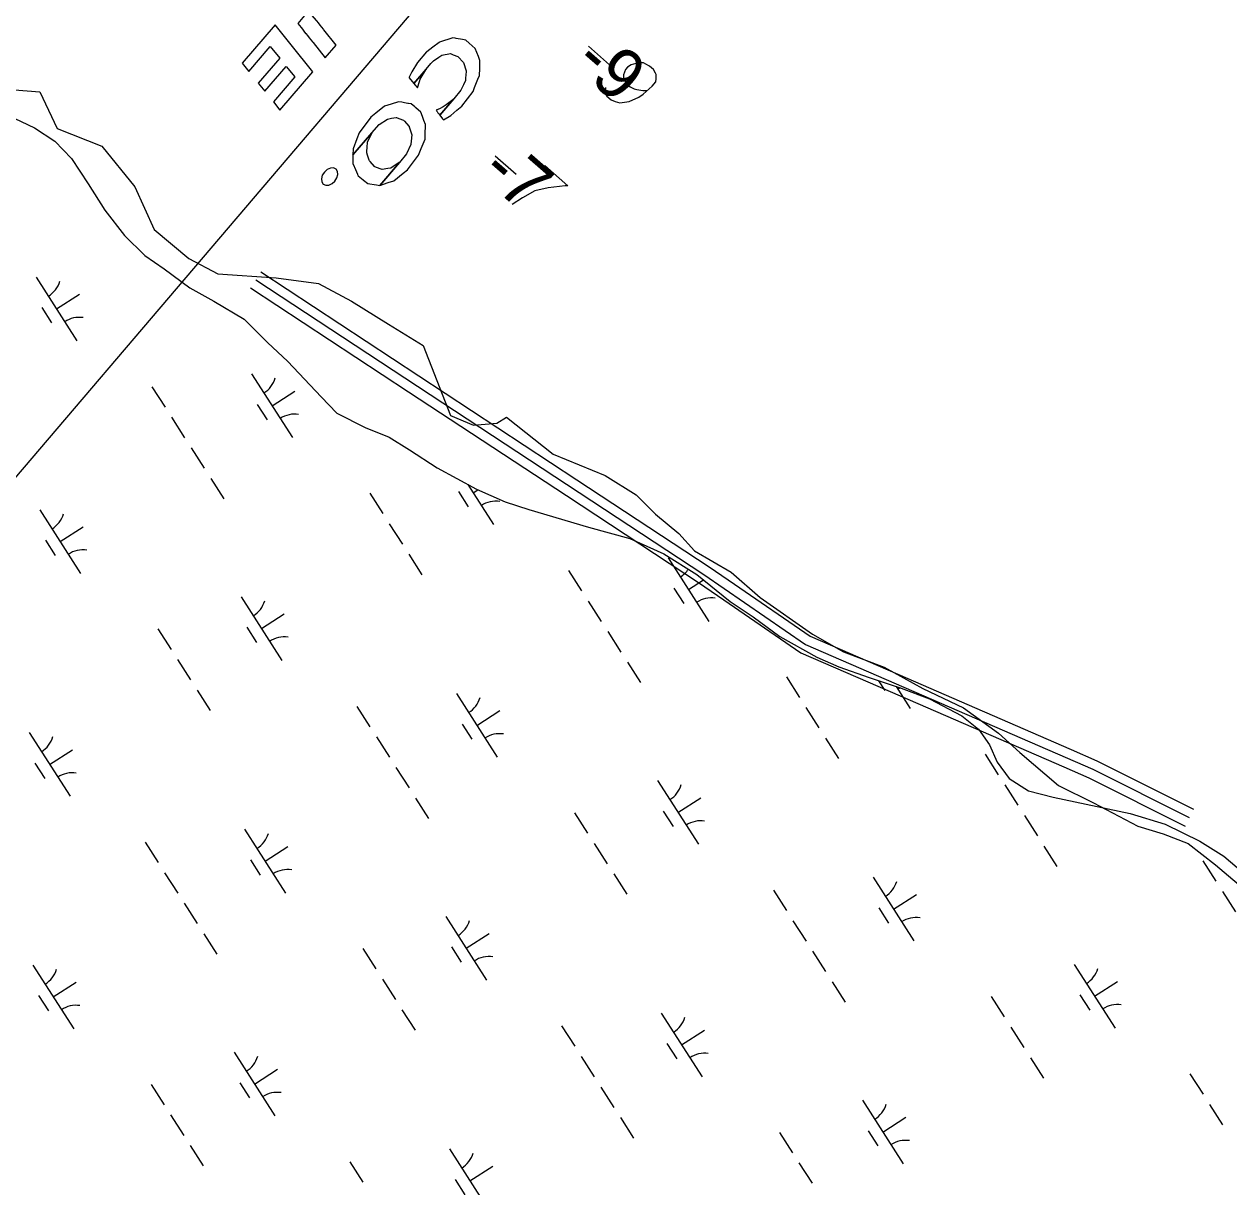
# Model space of a CAD drawing. Extents: x 3962991 to 3983549, y 181631 to 204078.
# Drawn here: x 3970099 to 3970895, y 195515 to 196284 of the extents above; entities that cross this region are included whole.
import ezdxf

# ---------------------------------------------------------------- set-up
doc = ezdxf.new("R2010")
doc.units = 0
for name, color, linetype in [('V-ANNO-MASK', 7, 'Continuous'), ('V-ANNO-MASK2', 7, 'Continuous'), ('V-RIVR-EDGE', 7, 'Continuous'), ('V-RIVR-IDEN', 7, 'Continuous'), ('V-RIVR-RANG', 7, 'Continuous'), ('V-UTIL-LINE', 7, 'Continuous'), ('V-WETL-SWMP', 7, 'Continuous')]:
    doc.layers.add(name, color=color, linetype=linetype)

msp = doc.modelspace()

# ---------------------------------------------------------------- linework, layer by layer
at = {"layer": 'V-ANNO-MASK2'}
for p, q in [((3970471.96, 196269.11), (3970485.89, 196256.98)), ((3970410.21, 196196.77), (3970424.14, 196184.65))]:
    msp.add_line(p, q, dxfattribs=at)
for points in [[(3970288.91, 196289.67), (3970286.47, 196292.07), (3970279.72, 196284.21), (3970281.89, 196281.5), (3970282.1, 196281.24), (3970284.93, 196277.7), (3970285.01, 196277.6), (3970286.13, 196276.2), (3970287.37, 196274.64), (3970289.48, 196272.02), (3970289.82, 196271.59), (3970289.82, 196271.59), (3970297.83, 196261.57), (3970305.05, 196269.96), (3970297.05, 196280.01), (3970296.72, 196280.44), (3970294.61, 196283.07), (3970293.37, 196284.63), (3970292.25, 196286.02), (3970292.17, 196286.12), (3970289.15, 196289.44)], [(3970269.16, 196277.88), (3970264.74, 196283.39), (3970242.98, 196258.08), (3970247.4, 196252.55), (3970261.57, 196269.05), (3970267.82, 196261.26), (3970253.64, 196244.77), (3970257.96, 196239.38), (3970272.13, 196255.87), (3970277.75, 196248.84), (3970263.58, 196232.35), (3970267.98, 196226.83), (3970289.74, 196252.15), (3970285.33, 196257.66), (3970279.71, 196264.69), (3970275.4, 196270.08)], [(3970365.05, 196265.51), (3970364.95, 196265.43), (3970358.93, 196258.33), (3970355.06, 196252.17), (3970353.47, 196248.63), (3970353.29, 196248.25), (3970356.52, 196244.5), (3970364.55, 196253.92), (3970367.81, 196257.67), (3970369.44, 196259.54), (3970373.12, 196261.95), (3970374.97, 196263.17), (3970380.72, 196264.29), (3970382.6, 196263.58), (3970385.57, 196262.45), (3970389.22, 196258.48), (3970389.29, 196258.4), (3970391.06, 196252.82), (3970390.83, 196249.85), (3970390.73, 196248.53), (3970390.69, 196248.04), (3970390.56, 196246.44), (3970389.28, 196243.63), (3970387.64, 196240.09), (3970382.99, 196234.37), (3970373.73, 196223.51), (3970375.46, 196221.25), (3970375.99, 196220.57), (3970380.86, 196223.32), (3970385.01, 196226.85), (3970388.23, 196229.6), (3970388.24, 196229.6), (3970395.64, 196239.32), (3970396.65, 196241.84), (3970398.89, 196247.44), (3970399.87, 196249.88), (3970400.03, 196254.36), (3970400.04, 196254.63), (3970400.1, 196256.33), (3970400.15, 196257.68), (3970400.2, 196259.19), (3970400.22, 196259.66), (3970399.9, 196260.48), (3970399.17, 196262.34), (3970397.12, 196267.58), (3970397.08, 196267.69), (3970393.05, 196271.22), (3970390.79, 196273.19), (3970388.63, 196273.58), (3970384.47, 196274.3), (3970383.76, 196274.43), (3970382.35, 196274.68), (3970382.32, 196274.68), (3970382.23, 196274.65), (3970373.35, 196271.78), (3970373.14, 196271.71), (3970369.04, 196268.57)], [(3970364.41, 196253.67), (3970364.55, 196253.92), (3970356.52, 196244.5), (3970356.56, 196244.47), (3970356.58, 196244.45), (3970357.39, 196243.5), (3970357.81, 196243.03), (3970358.89, 196241.75), (3970360.27, 196245.91), (3970360.78, 196247.48), (3970364.33, 196253.55)], [(3970331.33, 196224.88), (3970327.94, 196222.18), (3970320.3, 196211.94), (3970318.83, 196208.02), (3970316.35, 196201.42), (3970316.24, 196197.28), (3970328.68, 196211.87), (3970333.47, 196217.41), (3970339, 196221.03), (3970339.15, 196221.06), (3970341.61, 196221.54), (3970341.62, 196221.55), (3970344.75, 196222.16), (3970345.12, 196222.02), (3970346.66, 196221.44), (3970349.6, 196220.32), (3970349.8, 196220.1), (3970349.8, 196220.1), (3970350.29, 196219.57), (3970353.27, 196216.32), (3970353.27, 196216.32), (3970353.32, 196216.26), (3970353.41, 196215.96), (3970354.67, 196212.02), (3970355.1, 196210.68), (3970355.1, 196210.64), (3970354.76, 196206.36), (3970354.6, 196204.39), (3970354.59, 196204.3), (3970351.69, 196197.99), (3970351.67, 196197.95), (3970346.95, 196192.37), (3970334.02, 196177.2), (3970339.43, 196178.99), (3970343.31, 196180.28), (3970349.48, 196185.2), (3970352.25, 196187.4), (3970352.25, 196187.41), (3970359.65, 196197.13), (3970361.41, 196201.5), (3970363.88, 196207.68), (3970364.05, 196212.44), (3970364.06, 196212.48), (3970364.05, 196212.49), (3970364.17, 196215.53), (3970364.17, 196215.61), (3970364.23, 196217.47), (3970363.19, 196220.13), (3970363.18, 196220.17), (3970362.69, 196221.43), (3970361.23, 196225.14), (3970361.13, 196225.42), (3970361.09, 196225.5), (3970357.8, 196228.39), (3970357.26, 196228.86), (3970357.04, 196229.05), (3970354.81, 196231), (3970353.04, 196231.31), (3970352.61, 196231.39), (3970350.35, 196231.79), (3970348.56, 196232.1), (3970348.46, 196232.12), (3970346.33, 196232.49), (3970346.24, 196232.46), (3970341.51, 196230.93), (3970337.15, 196229.51)], [(3970372.87, 196227.58), (3970371.2, 196226.82), (3970371.68, 196226.19), (3970371.87, 196225.95), (3970372.45, 196225.19), (3970372.97, 196224.51), (3970373.63, 196223.65), (3970373.73, 196223.51), (3970382.99, 196234.37), (3970382.31, 196233.83), (3970377.95, 196230.34), (3970375.85, 196229.17), (3970373.5, 196227.87)], [(3970328.61, 196211.7), (3970328.68, 196211.87), (3970316.24, 196197.28), (3970316.24, 196197.19), (3970316.25, 196197.2), (3970316.17, 196194.25), (3970316.16, 196194.1), (3970316.17, 196194.1), (3970316.09, 196191.61), (3970316.99, 196189.59), (3970317.15, 196189.22), (3970317.15, 196189.22), (3970317.85, 196187.64), (3970319.18, 196184.63), (3970319.31, 196184.33), (3970319.62, 196183.61), (3970323.03, 196180.85), (3970323.09, 196180.8), (3970323.29, 196180.63), (3970326.02, 196178.42), (3970327.41, 196178.2), (3970327.44, 196178.2), (3970330.36, 196177.74), (3970331.71, 196177.53), (3970331.76, 196177.52), (3970333.95, 196177.18), (3970333.97, 196177.19), (3970334.02, 196177.2), (3970346.95, 196192.37), (3970346.88, 196192.33), (3970346.84, 196192.3), (3970341.26, 196188.66), (3970341.11, 196188.56), (3970339.35, 196188.28), (3970335.51, 196187.67), (3970335.49, 196187.68), (3970334.3, 196188.12), (3970330.78, 196189.41), (3970330.6, 196189.61), (3970330.55, 196189.67), (3970327.57, 196192.92), (3970327.08, 196193.45), (3970326.97, 196193.78), (3970325.9, 196197.08), (3970325.33, 196198.81), (3970325.37, 196199.43), (3970325.6, 196202.75), (3970325.77, 196205.37), (3970325.9, 196205.66)], [(3970299.22, 196187.69), (3970297.32, 196185.99), (3970295.94, 196183.84), (3970295.34, 196181.56), (3970295.54, 196179.53), (3970296.56, 196178.01), (3970298.23, 196177.24), (3970300.27, 196177.36), (3970302.39, 196178.34), (3970304.31, 196180.04), (3970305.67, 196182.19), (3970306.31, 196184.45), (3970306.1, 196186.48), (3970305.09, 196188.02), (3970303.42, 196188.77), (3970301.38, 196188.65)]]:
    msp.add_lwpolyline(points, close=True, dxfattribs=at)
for points in [[(3970483.2, 196241.84), (3970482.88, 196238.26), (3970484.16, 196236.11), (3970486.94, 196233.69), (3970489.62, 196232.75), (3970491.16, 196232.11), (3970492.68, 196231.84), (3970498.98, 196232.65), (3970505.32, 196235.52), (3970508.17, 196237.59), (3970513.99, 196242.67), (3970516.59, 196245.65), (3970516.83, 196247.54), (3970516.62, 196250.51), (3970516.37, 196251.43), (3970514.9, 196253.76), (3970512.32, 196256.01), (3970509.98, 196257.34), (3970508.24, 196258.16), (3970504.87, 196258.3), (3970500.11, 196256.85), (3970497.78, 196255.38), (3970496.39, 196253.78), (3970495.14, 196250.33), (3970495.07, 196248.64), (3970495.77, 196246.64), (3970497.63, 196243.96), (3970499.43, 196242.4), (3970502.13, 196241.1), (3970504.05, 196240.48), (3970507.82, 196239.99), (3970509.88, 196239.95), (3970511, 196240.03)], [(3970443.01, 196190.26), (3970458.33, 196176.92), (3970456.47, 196176.79), (3970445.33, 196175.65), (3970436.5, 196173.54), (3970428.4, 196169.05), (3970421.61, 196164.47)]]:
    msp.add_lwpolyline(points, dxfattribs=at)
at = {"layer": 'V-RIVR-EDGE'}
msp.add_lwpolyline([(3970092.49, 196240.33), (3970109.14, 196239.05), (3970120.67, 196214.72), (3970150.12, 196203.19), (3970171.89, 196176.3), (3970184.7, 196148.13), (3970207.75, 196128.92), (3970226.96, 196118.67), (3970265.38, 196116.11), (3970293.55, 196112.27), (3970315.32, 196100.74), (3970339.66, 196085.38), (3970362.71, 196071.29), (3970380.64, 196025.19), (3970396, 196018.78), (3970411.37, 196020.06), (3970417.77, 196023.91), (3970448.51, 195999.57), (3970483.09, 195985.49), (3970503.58, 195972.68), (3970516.38, 195959.87), (3970531.75, 195947.07), (3970542, 195935.54), (3970566.33, 195921.45), (3970585.54, 195904.81), (3970620.12, 195880.47), (3970640.61, 195868.95), (3970667.5, 195858.7), (3970693.11, 195844.62), (3970720.01, 195831.81), (3970743.06, 195815.16), (3970757.14, 195802.35), (3970782.76, 195780.58), (3970805.81, 195769.06), (3970835.26, 195753.69), (3970851.91, 195748.57), (3970868.56, 195742.16), (3970886.49, 195728.08), (3970910.82, 195707.59)], dxfattribs=at)
at = {"layer": 'V-RIVR-IDEN'}
for points in [[(3970255.39, 196119.94), (3970359.84, 196051.27), (3970464.3, 195982.61)], [(3970248.53, 196109.49), (3970352.98, 196040.82), (3970457.43, 195972.16)], [(3970251.96, 196114.71), (3970548.23, 195919.95), (3970615.53, 195873.71), (3970805.53, 195791.24), (3970869.23, 195759.32)], [(3970464.3, 195982.61), (3970551.71, 195925.14), (3970568.62, 195913.53)], [(3970457.43, 195972.16), (3970544.74, 195914.76), (3970561.54, 195903.22)], [(3970568.62, 195913.53), (3970618.58, 195879.21), (3970676.54, 195854.05)], [(3970561.54, 195903.22), (3970612.49, 195868.22), (3970671.56, 195842.58)], [(3970676.53, 195854.05), (3970791.2, 195804.27)], [(3970671.56, 195842.58), (3970786.22, 195792.8)], [(3970791.2, 195804.27), (3970808.17, 195796.9), (3970872.03, 195764.91)], [(3970786.22, 195792.8), (3970802.88, 195785.57), (3970866.43, 195753.73)]]:
    msp.add_lwpolyline(points, dxfattribs=at)
at = {"layer": 'V-UTIL-LINE'}
msp.add_line((3970065.58, 195951.74), (3971473.5, 197603.23), dxfattribs=at)
at = {"layer": 'V-WETL-SWMP'}
for p, q in [((3970088.04, 196223.57), (3970105.67, 196215.32)), ((3970105.67, 196215.32), (3970119.07, 196206.41)), ((3970119.07, 196206.41), (3970130.08, 196195.05)), ((3970130.08, 196195.05), (3970141.15, 196178.26)), ((3970141.15, 196178.26), (3970152.24, 196160.86)), ((3970152.24, 196160.86), (3970165.12, 196144.09)), ((3970165.12, 196144.09), (3970178.57, 196130.95)), ((3970178.57, 196130.95), (3970191.37, 196122.03)), ((3970191.37, 196122.03), (3970208.44, 196109.54)), ((3970106.76, 196116.53), (3970133.74, 196074.44)), ((3970208.44, 196109.54), (3970224.26, 196100.65)), ((3970120.25, 196095.49), (3970135.4, 196105.2)), ((3970110.52, 196096.38), (3970116.99, 196086.27)), ((3970224.26, 196100.65), (3970244.34, 196088.8)), ((3970244.34, 196088.8), (3970259.63, 196073.26)), ((3970259.63, 196073.26), (3970273.07, 196060.73)), ((3970273.07, 196060.73), (3970295.1, 196037.41)), ((3970249.21, 196052.58), (3970276.19, 196010.49)), ((3970183.32, 196044.11), (3970191.96, 196030.64)), ((3970262.7, 196031.54), (3970277.85, 196041.25)), ((3970295.1, 196037.41), (3970305.5, 196026.65)), ((3970252.96, 196032.42), (3970259.44, 196022.32)), ((3970196.28, 196023.9), (3970204.91, 196010.43)), ((3970305.5, 196026.65), (3970324.35, 196017.2)), ((3970324.35, 196017.2), (3970340.14, 196010.74)), ((3970340.14, 196010.74), (3970353.53, 196002.43)), ((3970209.23, 196003.7), (3970217.87, 195990.23)), ((3970353.53, 196002.43), (3970371.81, 195990.56)), ((3970371.81, 195990.56), (3970397.96, 195976.36)), ((3970222.18, 195983.5), (3970230.82, 195970.03)), ((3970327.32, 195973.74), (3970335.96, 195960.28)), ((3970385.99, 195974.88), (3970392.47, 195964.78)), ((3970392.2, 195979.48), (3970409.21, 195952.95)), ((3970395.72, 195974), (3970398.82, 195975.98)), ((3970397.96, 195976.36), (3970416.79, 195968.11)), ((3970416.79, 195968.11), (3970432.57, 195962.86)), ((3970109.17, 195962.81), (3970136.16, 195920.72)), ((3970432.57, 195962.86), (3970471.99, 195951.23)), ((3970122.67, 195941.76), (3970137.82, 195951.48)), ((3970340.28, 195953.54), (3970348.91, 195940.07)), ((3970471.99, 195951.23), (3970499.27, 195943.69)), ((3970112.93, 195942.65), (3970119.41, 195932.55)), ((3970499.27, 195943.69), (3970521.75, 195933.68)), ((3970521.75, 195933.68), (3970543.67, 195920.03)), ((3970353.23, 195933.34), (3970361.87, 195919.87)), ((3970524.68, 195931.09), (3970551.66, 195889)), ((3970458.8, 195922.62), (3970467.43, 195909.15)), ((3970543.67, 195920.03), (3970565.64, 195902.16)), ((3970528.44, 195910.93), (3970534.91, 195900.83)), ((3970538.17, 195910.04), (3970548.11, 195916.42)), ((3970242.2, 195905.27), (3970269.18, 195863.18)), ((3970471.75, 195902.41), (3970480.39, 195888.94)), ((3970565.64, 195902.16), (3970580.87, 195892.06)), ((3970255.69, 195884.22), (3970270.84, 195893.94)), ((3970580.87, 195892.06), (3970598.55, 195878.97)), ((3970187.29, 195883.97), (3970195.93, 195870.5)), ((3970245.96, 195885.11), (3970252.43, 195875.01)), ((3970484.7, 195882.21), (3970493.34, 195868.74)), ((3970598.55, 195878.97), (3970622.88, 195865.35)), ((3970200.25, 195863.77), (3970208.88, 195850.3)), ((3970497.66, 195862), (3970506.29, 195848.53)), ((3970622.88, 195865.35), (3970637.46, 195858.87)), ((3970637.46, 195858.87), (3970657.49, 195851.85)), ((3970602.8, 195852.25), (3970611.43, 195838.78)), ((3970657.49, 195851.85), (3970678.73, 195844.85)), ((3970663.78, 195849.78), (3970667.94, 195843.29)), ((3970213.2, 195843.56), (3970221.83, 195830.09)), ((3970384.65, 195841.32), (3970411.63, 195799.22)), ((3970675.4, 195845.94), (3970684.69, 195831.46)), ((3970678.73, 195844.85), (3970697.54, 195837.81)), ((3970318.77, 195832.84), (3970327.4, 195819.37)), ((3970615.75, 195832.05), (3970624.39, 195818.58)), ((3970697.54, 195837.81), (3970718.83, 195826.58)), ((3970398.14, 195820.27), (3970413.29, 195829.99)), ((3970718.83, 195826.58), (3970729.81, 195817.64)), ((3970102.17, 195815.49), (3970129.15, 195773.4)), ((3970388.41, 195821.16), (3970394.88, 195811.06)), ((3970729.81, 195817.64), (3970737.18, 195807.45)), ((3970331.72, 195812.64), (3970340.35, 195799.17)), ((3970628.7, 195811.84), (3970637.34, 195798.37)), ((3970737.18, 195807.45), (3970742.15, 195796.02)), ((3970115.66, 195794.45), (3970130.81, 195804.16)), ((3970734.27, 195801.12), (3970742.91, 195787.65)), ((3970105.93, 195795.34), (3970112.4, 195785.23)), ((3970344.67, 195792.43), (3970353.31, 195778.96)), ((3970742.15, 195796.02), (3970750.14, 195785.24)), ((3970517.67, 195783.78), (3970544.66, 195741.68)), ((3970750.14, 195785.24), (3970762.92, 195776.93)), ((3970747.22, 195780.92), (3970755.86, 195767.45)), ((3970762.92, 195776.93), (3970779.29, 195772.89)), ((3970357.63, 195772.23), (3970366.26, 195758.76)), ((3970531.16, 195762.73), (3970546.32, 195772.44)), ((3970779.29, 195772.89), (3970830.19, 195762)), ((3970462.77, 195762.48), (3970471.4, 195749.01)), ((3970521.43, 195763.62), (3970527.91, 195753.51)), ((3970760.18, 195760.71), (3970768.81, 195747.24)), ((3970830.19, 195762), (3970853.23, 195755.01)), ((3970244.62, 195751.54), (3970271.6, 195709.45)), ((3970853.23, 195755.01), (3970876.33, 195743.8)), ((3970178.73, 195743.07), (3970187.37, 195729.6)), ((3970876.33, 195743.8), (3970892.17, 195733.71)), ((3970258.11, 195730.5), (3970273.26, 195740.21)), ((3970475.72, 195742.27), (3970484.35, 195728.8)), ((3970773.13, 195740.51), (3970781.77, 195727.04)), ((3970248.37, 195731.38), (3970254.85, 195721.28)), ((3970878.27, 195730.76), (3970886.91, 195717.29)), ((3970892.17, 195733.71), (3970906.82, 195721.18)), ((3970191.69, 195722.86), (3970200.32, 195709.4)), ((3970488.67, 195722.07), (3970497.31, 195708.6)), ((3970660.12, 195719.82), (3970687.11, 195677.73)), ((3970594.24, 195711.35), (3970602.87, 195697.88)), ((3970891.22, 195710.55), (3970899.86, 195697.08)), ((3970204.64, 195702.66), (3970213.28, 195689.19)), ((3970673.61, 195698.78), (3970688.77, 195708.49)), ((3970663.88, 195699.66), (3970670.36, 195689.56)), ((3970377.64, 195694), (3970404.62, 195651.91)), ((3970607.19, 195691.15), (3970615.83, 195677.68)), ((3970217.59, 195682.46), (3970226.23, 195668.99)), ((3970391.13, 195672.96), (3970406.29, 195682.67)), ((3970322.73, 195672.7), (3970331.37, 195659.24)), ((3970381.4, 195673.84), (3970387.87, 195663.74)), ((3970620.15, 195670.94), (3970628.78, 195657.47)), ((3970104.58, 195661.77), (3970131.57, 195619.68)), ((3970793.14, 195662.28), (3970820.13, 195620.19)), ((3970118.08, 195640.72), (3970133.23, 195650.44)), ((3970335.69, 195652.5), (3970344.32, 195639.03)), ((3970633.1, 195650.74), (3970641.73, 195637.27)), ((3970806.64, 195641.24), (3970821.79, 195650.95)), ((3970108.34, 195641.61), (3970114.82, 195631.51)), ((3970738.24, 195640.99), (3970746.87, 195627.52)), ((3970796.9, 195642.12), (3970803.38, 195632.02)), ((3970348.64, 195632.3), (3970357.28, 195618.83)), ((3970520.09, 195630.05), (3970547.07, 195587.96)), ((3970454.21, 195621.58), (3970462.84, 195608.11)), ((3970533.58, 195609), (3970548.73, 195618.72)), ((3970751.19, 195620.78), (3970759.83, 195607.31)), ((3970523.85, 195609.89), (3970530.32, 195599.79)), ((3970237.61, 195604.23), (3970264.59, 195562.14)), ((3970467.16, 195601.37), (3970475.8, 195587.9)), ((3970764.15, 195600.58), (3970772.78, 195587.11)), ((3970251.1, 195583.18), (3970266.25, 195592.9)), ((3970241.37, 195584.07), (3970247.84, 195573.97)), ((3970869.71, 195589.86), (3970878.35, 195576.39)), ((3970182.7, 195582.93), (3970191.34, 195569.46)), ((3970480.11, 195581.17), (3970488.75, 195567.7)), ((3970653.11, 195572.51), (3970680.1, 195530.42)), ((3970882.67, 195569.65), (3970891.3, 195556.18)), ((3970195.66, 195562.73), (3970204.29, 195549.26)), ((3970493.07, 195560.96), (3970501.7, 195547.49)), ((3970666.61, 195551.46), (3970681.76, 195561.18)), ((3970598.21, 195551.21), (3970606.84, 195537.74)), ((3970656.87, 195552.35), (3970663.35, 195542.25)), ((3970208.61, 195542.52), (3970217.24, 195529.05)), ((3970380.06, 195540.28), (3970407.04, 195498.18)), ((3970314.18, 195531.8), (3970322.81, 195518.33)), ((3970393.55, 195519.23), (3970408.7, 195528.95)), ((3970611.16, 195531.01), (3970619.8, 195517.54)), ((3970383.82, 195520.12), (3970390.29, 195510.02))]:
    msp.add_line(p, q, dxfattribs=at)
for centre, start, end in [((3970105.54, 196118.87), 301.89187, 343.43553), ((3970135.36, 196072.36), 81.89186, 123.43552), ((3970247.99, 196054.92), 301.89187, 343.43553), ((3970277.81, 196008.41), 81.89186, 123.43552), ((3970410.83, 195950.87), 81.89186, 123.43552), ((3970107.96, 195965.15), 301.89187, 343.43553), ((3970137.77, 195918.64), 81.89186, 123.43552), ((3970523.46, 195933.43), 301.89187, 325.85548), ((3970240.98, 195907.6), 301.89187, 343.43553), ((3970553.28, 195886.92), 81.89186, 123.43552), ((3970270.8, 195861.1), 81.89186, 123.43552), ((3970383.43, 195843.65), 301.89187, 343.43553), ((3970686.3, 195829.38), 117.40264, 123.43552), ((3970413.25, 195797.15), 81.89186, 123.43552), ((3970100.95, 195817.83), 301.89187, 343.43553), ((3970130.77, 195771.32), 81.89186, 123.43552), ((3970516.46, 195786.11), 301.89187, 343.43553), ((3970546.27, 195739.6), 81.89186, 123.43552), ((3970243.4, 195753.88), 301.89187, 343.43553), ((3970273.22, 195707.37), 81.89186, 123.43552), ((3970658.91, 195722.16), 301.89187, 343.43553), ((3970376.42, 195696.34), 301.89187, 343.43553), ((3970688.72, 195675.65), 81.89186, 123.43552), ((3970406.24, 195649.83), 81.89186, 123.43552), ((3970103.37, 195664.11), 301.89187, 343.43553), ((3970791.93, 195664.62), 301.89187, 343.43553), ((3970133.18, 195617.6), 81.89186, 123.43552), ((3970821.74, 195618.11), 81.89186, 123.43552), ((3970518.87, 195632.39), 301.89187, 343.43553), ((3970236.39, 195606.56), 301.89187, 343.43553), ((3970548.69, 195585.88), 81.89186, 123.43552), ((3970266.21, 195560.06), 81.89186, 123.43552), ((3970651.9, 195574.84), 301.89187, 343.43553), ((3970681.71, 195528.34), 81.89186, 123.43552), ((3970378.84, 195542.61), 301.89187, 343.43553)]:
    msp.add_arc(centre, 17.62, start, end, dxfattribs=at)

# ---------------------------------------------------------------- texts
at = {"layer": 'V-ANNO-MASK'}
for s, p in [('-9', (3970460.88, 196256.37)), ('-7', (3970399.13, 196184.04))]:
    msp.add_text(s, height=33.5, rotation=318.96581, dxfattribs=at).set_placement(p)
at = {"layer": 'V-RIVR-RANG'}
for s, p in [('-9', (3970460.88, 196256.37)), ('-7', (3970399.13, 196184.04))]:
    msp.add_text(s, height=33.5, rotation=318.96581, dxfattribs=at).set_placement(p)

doc.saveas('drawing.dxf')
